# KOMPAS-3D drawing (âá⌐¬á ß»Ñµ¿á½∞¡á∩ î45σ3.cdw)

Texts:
  Гайка специальная
  Microsoft
  Текст на чертеже
  Размерные надписи
  Шероховатость
  Линия-выноска #1
  Линия-выноска #2
  Линия-выноска #3
  Отклонения формы и база
  Заголовок таблицы
  Ячейка таблицы
  Стрелка вида
  Обозначение изменения
  Фигурная скобка
  Номер узла
  Марка координационной оси
  VRCB
  Выносная надпись
  Обозначение узла
  Марка/позиционное обозначение с линией-выноской
  Марка/позиционное обозначение на линии
  Марка/позиционное обозначение без линии-выноски
  1.Н14; h14 ;   IT14 2 .
  Rz 40
  Сталь 45 ГОСТ 1050-88
Dimensions and other numbers on the sheet: 7; 60; 8; 10; 1,5; 2 фаски; 1; 45х3; 35; 1:1; 0; 2; 3; 4; 5; 6; 9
